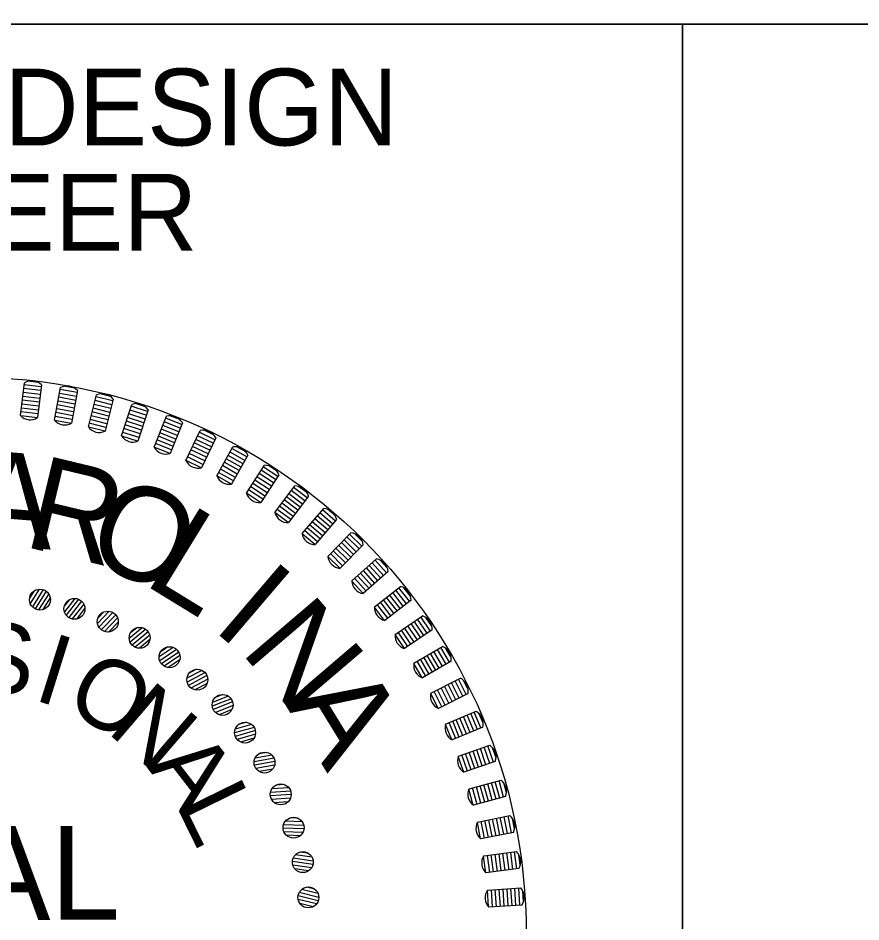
# Model space of a CAD drawing. Extents: x 2111095 to 2115970, y 670428 to 672393.
# Drawn here: x 2113107.3 to 2113162.1, y 672107.5 to 672166.4 of the extents above; entities that cross this region are included whole.
import ezdxf

# ---------------------------------------------------------------- set-up
doc = ezdxf.new("R2010")
doc.units = 0
doc.layers.add('Sheet PE Seal Cell', color=7, linetype='Continuous')
doc.layers.add('Sheet Typical CELL', color=7, linetype='Continuous')

msp = doc.modelspace()

# ---------------------------------------------------------------- linework, layer by layer
at = {"layer": 'Sheet PE Seal Cell'}
for p, q in [((2113107.43, 672140.486), (2113107.679, 672142.629)), ((2113108.585, 672142.648), (2113107.91, 672142.727)), ((2113108.714, 672141.864), (2113107.605, 672141.993)), ((2113108.743, 672142.117), (2113107.634, 672142.246)), ((2113108.773, 672142.37), (2113107.664, 672142.499)), ((2113108.788, 672142.501), (2113108.539, 672140.357)), ((2113109.651, 672140.191), (2113110.041, 672142.313)), ((2113111.115, 672141.982), (2113110.017, 672142.184)), ((2113110.946, 672142.272), (2113110.277, 672142.395)), ((2113111.138, 672142.112), (2113110.749, 672139.989)), ((2113108.655, 672141.358), (2113107.546, 672141.487)), ((2113108.685, 672141.611), (2113107.576, 672141.74)), ((2113110.977, 672141.231), (2113109.879, 672141.432)), ((2113111.023, 672141.481), (2113109.925, 672141.683)), ((2113111.069, 672141.732), (2113109.971, 672141.933)), ((2113111.847, 672139.749), (2113112.376, 672141.842)), ((2113113.363, 672141.193), (2113112.281, 672141.467)), ((2113113.426, 672141.44), (2113112.344, 672141.714)), ((2113113.277, 672141.741), (2113112.618, 672141.908)), ((2113113.458, 672141.568), (2113112.929, 672139.476)), ((2113108.597, 672140.852), (2113107.488, 672140.98)), ((2113108.626, 672141.105), (2113107.517, 672141.234)), ((2113110.885, 672140.73), (2113109.787, 672140.931)), ((2113110.931, 672140.98), (2113109.833, 672141.182)), ((2113113.239, 672140.7), (2113112.156, 672140.973)), ((2113113.301, 672140.947), (2113112.219, 672141.22)), ((2113114.009, 672139.164), (2113114.675, 672141.217)), ((2113115.618, 672140.505), (2113114.556, 672140.849)), ((2113115.696, 672140.747), (2113114.635, 672141.092)), ((2113115.567, 672141.057), (2113114.921, 672141.267)), ((2113115.737, 672140.872), (2113115.071, 672138.819)), ((2113108.524, 672140.347), (2113107.443, 672140.473)), ((2113108.567, 672140.599), (2113107.458, 672140.727)), ((2113110.793, 672140.228), (2113109.695, 672140.43)), ((2113110.839, 672140.479), (2113109.741, 672140.681)), ((2113113.051, 672139.959), (2113111.969, 672140.232)), ((2113113.114, 672140.206), (2113112.031, 672140.479)), ((2113113.176, 672140.453), (2113112.094, 672140.726)), ((2113115.46, 672140.02), (2113114.399, 672140.365)), ((2113115.539, 672140.263), (2113114.477, 672140.607)), ((2113116.127, 672138.437), (2113116.928, 672140.441)), ((2113117.916, 672139.905), (2113116.879, 672140.319)), ((2113117.808, 672140.223), (2113117.176, 672140.475)), ((2113110.733, 672139.98), (2113109.662, 672140.177)), ((2113112.913, 672139.468), (2113111.857, 672139.735)), ((2113112.989, 672139.712), (2113111.906, 672139.986)), ((2113115.224, 672139.293), (2113114.163, 672139.638)), ((2113115.303, 672139.536), (2113114.241, 672139.88)), ((2113115.382, 672139.778), (2113114.32, 672140.123)), ((2113117.727, 672139.432), (2113116.69, 672139.846)), ((2113117.821, 672139.669), (2113116.785, 672140.083)), ((2113117.965, 672140.027), (2113117.164, 672138.023)), ((2113115.054, 672138.813), (2113114.019, 672139.149)), ((2113115.146, 672139.051), (2113114.084, 672139.396)), ((2113117.443, 672138.722), (2113116.407, 672139.137)), ((2113117.538, 672138.959), (2113116.501, 672139.373)), ((2113117.632, 672139.196), (2113116.596, 672139.61)), ((2113118.193, 672137.572), (2113119.125, 672139.519)), ((2113119.965, 672138.689), (2113118.958, 672139.17)), ((2113120.075, 672138.918), (2113119.068, 672139.4)), ((2113119.988, 672139.242), (2113119.375, 672139.536)), ((2113117.254, 672138.249), (2113116.218, 672138.663)), ((2113117.349, 672138.486), (2113116.312, 672138.9)), ((2113119.635, 672137.999), (2113118.628, 672138.481)), ((2113119.745, 672138.229), (2113118.738, 672138.711)), ((2113119.855, 672138.459), (2113118.848, 672138.941)), ((2113120.132, 672139.037), (2113119.2, 672137.09)), ((2113120.198, 672136.572), (2113121.256, 672138.453)), ((2113122.099, 672138.12), (2113121.506, 672138.453)), ((2113117.147, 672138.018), (2113116.136, 672138.422)), ((2113119.416, 672137.54), (2113118.409, 672138.021)), ((2113119.525, 672137.77), (2113118.518, 672138.251)), ((2113121.914, 672137.347), (2113120.942, 672137.894)), ((2113122.039, 672137.569), (2113121.066, 672138.116)), ((2113122.229, 672137.906), (2113121.171, 672136.025)), ((2113122.164, 672137.791), (2113121.191, 672138.338)), ((2113119.183, 672137.086), (2113118.201, 672137.556)), ((2113119.306, 672137.31), (2113118.299, 672137.792)), ((2113121.665, 672136.903), (2113120.692, 672137.45)), ((2113121.79, 672137.125), (2113120.817, 672137.672)), ((2113121.29, 672136.237), (2113120.317, 672136.784)), ((2113121.415, 672136.459), (2113120.442, 672137.006)), ((2113121.54, 672136.681), (2113120.567, 672137.228)), ((2113122.132, 672135.442), (2113123.312, 672137.249)), ((2113123.896, 672136.102), (2113122.961, 672136.712)), ((2113124.035, 672136.315), (2113123.1, 672136.925)), ((2113124.174, 672136.528), (2113123.24, 672137.139)), ((2113124.131, 672136.861), (2113123.562, 672137.233)), ((2113121.153, 672136.022), (2113120.204, 672136.555)), ((2113123.617, 672135.675), (2113122.683, 672136.286)), ((2113123.757, 672135.888), (2113122.822, 672136.499)), ((2113124.246, 672136.638), (2113123.066, 672134.831)), ((2113123.199, 672135.035), (2113122.265, 672135.646)), ((2113123.339, 672135.249), (2113122.404, 672135.859)), ((2113123.478, 672135.462), (2113122.543, 672136.072)), ((2113123.987, 672134.186), (2113125.283, 672135.911)), ((2113125.943, 672134.932), (2113125.051, 672135.603)), ((2113126.097, 672135.135), (2113125.204, 672135.806)), ((2113126.075, 672135.47), (2113125.532, 672135.879)), ((2113123.049, 672134.83), (2113122.137, 672135.425)), ((2113125.484, 672134.321), (2113124.592, 672134.992)), ((2113125.637, 672134.525), (2113124.745, 672135.195)), ((2113126.176, 672135.24), (2113124.879, 672133.515)), ((2113125.79, 672134.728), (2113124.898, 672135.399)), ((2113125.025, 672133.71), (2113124.133, 672134.381)), ((2113125.178, 672133.914), (2113124.286, 672134.584)), ((2113125.331, 672134.117), (2113124.439, 672134.788)), ((2113125.754, 672132.811), (2113127.162, 672134.446)), ((2113127.923, 672133.618), (2113127.077, 672134.347)), ((2113127.923, 672133.954), (2113127.408, 672134.397)), ((2113124.861, 672133.515), (2113123.991, 672134.169)), ((2113127.424, 672133.039), (2113126.578, 672133.768)), ((2113127.59, 672133.232), (2113126.744, 672133.961)), ((2113127.756, 672133.425), (2113126.91, 672134.154)), ((2113126.925, 672132.46), (2113126.079, 672133.188)), ((2113127.092, 672132.653), (2113126.246, 672133.381)), ((2113127.258, 672132.846), (2113126.412, 672133.574)), ((2113128.008, 672133.718), (2113126.6, 672132.082)), ((2113126.583, 672132.083), (2113125.758, 672132.793)), ((2113126.759, 672132.267), (2113125.913, 672132.995)), ((2113127.427, 672131.321), (2113128.94, 672132.86)), ((2113129.466, 672131.802), (2113128.67, 672132.585)), ((2113129.644, 672131.984), (2113128.848, 672132.767)), ((2113129.667, 672132.319), (2113129.182, 672132.795)), ((2113128.93, 672131.257), (2113128.134, 672132.04)), ((2113129.736, 672132.078), (2113128.223, 672130.539)), ((2113129.109, 672131.439), (2113128.313, 672132.222)), ((2113129.287, 672131.621), (2113128.491, 672132.403)), ((2113128.394, 672130.713), (2113127.598, 672131.495)), ((2113128.573, 672130.894), (2113127.777, 672131.677)), ((2113128.751, 672131.076), (2113127.955, 672131.858)), ((2113128.206, 672130.541), (2113127.429, 672131.304)), ((2113128.998, 672129.725), (2113130.61, 672131.16)), ((2113131.064, 672130.07), (2113130.321, 672130.904)), ((2113131.254, 672130.24), (2113130.512, 672131.073)), ((2113131.299, 672130.572), (2113130.847, 672131.08)), ((2113130.303, 672129.392), (2113129.561, 672130.226)), ((2113131.352, 672130.327), (2113129.741, 672128.891)), ((2113130.493, 672129.562), (2113129.751, 672130.395)), ((2113130.684, 672129.731), (2113129.941, 672130.565)), ((2113130.874, 672129.901), (2113130.131, 672130.734)), ((2113129.723, 672128.894), (2113128.999, 672129.707)), ((2113129.923, 672129.053), (2113129.18, 672129.887)), ((2113130.113, 672129.223), (2113129.37, 672130.056)), ((2113108.311, 672129.066), (2113108.02, 672128.6)), ((2113108.651, 672129.183), (2113108.065, 672128.243)), ((2113108.9, 672129.152), (2113108.201, 672128.034)), ((2113109.102, 672129.048), (2113108.384, 672127.897)), ((2113130.461, 672128.028), (2113132.163, 672129.354)), ((2113132.544, 672128.236), (2113131.859, 672129.117)), ((2113132.745, 672128.392), (2113132.059, 672129.273)), ((2113132.812, 672128.721), (2113132.395, 672129.258)), ((2113109.263, 672128.877), (2113108.608, 672127.828)), ((2113109.366, 672128.613), (2113108.89, 672127.852)), ((2113110.618, 672128.502), (2113110.28, 672128.069)), ((2113110.968, 672128.582), (2113110.287, 672127.709)), ((2113111.212, 672128.526), (2113110.401, 672127.487)), ((2113131.74, 672127.61), (2113131.055, 672128.491)), ((2113132.849, 672128.473), (2113131.146, 672127.147)), ((2113131.941, 672127.766), (2113131.256, 672128.647)), ((2113132.142, 672127.923), (2113131.457, 672128.804)), ((2113132.343, 672128.079), (2113131.658, 672128.96)), ((2113111.402, 672128.401), (2113110.568, 672127.332)), ((2113111.544, 672128.214), (2113110.783, 672127.24)), ((2113111.619, 672127.941), (2113111.066, 672127.234)), ((2113131.129, 672127.151), (2113130.46, 672128.01)), ((2113131.339, 672127.297), (2113130.653, 672128.178)), ((2113131.54, 672127.453), (2113130.854, 672128.334)), ((2113113.21, 672127.743), (2113112.441, 672126.946)), ((2113112.853, 672127.7), (2113112.471, 672127.304)), ((2113113.446, 672127.661), (2113112.531, 672126.713)), ((2113113.623, 672127.517), (2113112.681, 672126.542)), ((2113113.744, 672127.317), (2113112.886, 672126.427)), ((2113131.807, 672126.238), (2113133.594, 672127.449)), ((2113134.111, 672126.451), (2113133.485, 672127.375)), ((2113134.2, 672126.774), (2113133.818, 672127.337)), ((2113113.79, 672127.037), (2113113.166, 672126.391)), ((2113133.268, 672125.879), (2113132.641, 672126.803)), ((2113133.479, 672126.022), (2113132.852, 672126.946)), ((2113133.689, 672126.165), (2113133.063, 672127.089)), ((2113133.9, 672126.308), (2113133.274, 672127.232)), ((2113115.351, 672126.674), (2113114.503, 672125.962)), ((2113115.578, 672126.568), (2113114.568, 672125.72)), ((2113114.991, 672126.668), (2113114.571, 672126.315)), ((2113115.738, 672126.407), (2113114.699, 672125.534)), ((2113115.838, 672126.194), (2113114.891, 672125.399)), ((2113132.416, 672125.319), (2113131.806, 672126.22)), ((2113132.635, 672125.451), (2113132.009, 672126.375)), ((2113132.846, 672125.593), (2113132.22, 672126.518)), ((2113133.057, 672125.736), (2113132.431, 672126.66)), ((2113134.22, 672126.525), (2113132.433, 672125.314)), ((2113115.854, 672125.912), (2113115.167, 672125.334)), ((2113117.369, 672125.387), (2113116.451, 672124.768)), ((2113117.583, 672125.258), (2113116.49, 672124.52)), ((2113117.011, 672125.419), (2113116.555, 672125.112)), ((2113117.726, 672125.081), (2113116.602, 672124.322)), ((2113133.033, 672124.363), (2113134.895, 672125.453)), ((2113134.686, 672124.037), (2113134.122, 672125.001)), ((2113134.906, 672124.166), (2113134.342, 672125.129)), ((2113135.126, 672124.294), (2113134.562, 672125.258)), ((2113135.346, 672124.423), (2113134.782, 672125.387)), ((2113135.455, 672124.74), (2113135.112, 672125.327)), ((2113117.803, 672124.859), (2113116.778, 672124.167)), ((2113117.79, 672124.576), (2113117.046, 672124.074)), ((2113133.58, 672123.406), (2113133.03, 672124.346)), ((2113133.807, 672123.523), (2113133.243, 672124.486)), ((2113134.026, 672123.651), (2113133.463, 672124.615)), ((2113135.459, 672124.489), (2113133.596, 672123.4)), ((2113134.246, 672123.78), (2113133.683, 672124.743)), ((2113134.466, 672123.909), (2113133.902, 672124.872)), ((2113119.241, 672123.896), (2113118.264, 672123.376)), ((2113119.441, 672123.746), (2113118.277, 672123.126)), ((2113118.888, 672123.965), (2113118.403, 672123.707)), ((2113119.564, 672123.554), (2113118.367, 672122.917)), ((2113119.618, 672123.326), (2113118.526, 672122.745)), ((2113134.132, 672122.411), (2113136.062, 672123.376)), ((2113136.216, 672122.204), (2113135.717, 672123.203)), ((2113136.443, 672122.318), (2113135.945, 672123.317)), ((2113136.574, 672122.627), (2113136.27, 672123.236)), ((2113119.575, 672123.046), (2113118.782, 672122.624)), ((2113135.076, 672121.635), (2113134.577, 672122.634)), ((2113135.304, 672121.749), (2113134.805, 672122.748)), ((2113135.532, 672121.863), (2113135.033, 672122.862)), ((2113135.76, 672121.977), (2113135.261, 672122.975)), ((2113135.988, 672122.091), (2113135.489, 672123.089)), ((2113121.13, 672122.047), (2113119.908, 672121.553)), ((2113120.947, 672122.218), (2113119.921, 672121.803)), ((2113120.604, 672122.324), (2113120.094, 672122.118)), ((2113134.614, 672121.42), (2113134.128, 672122.394)), ((2113134.848, 672121.522), (2113134.349, 672122.52)), ((2113136.561, 672122.377), (2113134.63, 672121.413)), ((2113121.233, 672121.844), (2113119.976, 672121.336)), ((2113121.262, 672121.611), (2113120.116, 672121.148)), ((2113121.19, 672121.337), (2113120.358, 672121.001)), ((2113135.099, 672120.391), (2113137.089, 672121.226)), ((2113136.695, 672119.85), (2113136.263, 672120.879)), ((2113136.93, 672119.948), (2113136.498, 672120.978)), ((2113137.165, 672120.047), (2113136.733, 672121.076)), ((2113137.4, 672120.145), (2113136.968, 672121.175)), ((2113137.55, 672120.445), (2113137.287, 672121.072)), ((2113122.469, 672120.37), (2113121.405, 672120.065)), ((2113122.138, 672120.511), (2113121.61, 672120.36)), ((2113135.515, 672119.37), (2113135.094, 672120.374)), ((2113135.755, 672119.456), (2113135.324, 672120.485)), ((2113135.99, 672119.554), (2113135.559, 672120.584)), ((2113136.225, 672119.653), (2113135.793, 672120.682)), ((2113136.46, 672119.751), (2113136.028, 672120.781)), ((2113122.633, 672120.181), (2113121.366, 672119.818)), ((2113122.714, 672119.969), (2113121.41, 672119.594)), ((2113122.719, 672119.734), (2113121.53, 672119.393)), ((2113137.521, 672120.196), (2113135.531, 672119.362)), ((2113122.618, 672119.469), (2113121.756, 672119.222)), ((2113123.475, 672118.549), (2113122.934, 672118.453)), ((2113135.931, 672118.311), (2113137.972, 672119.013)), ((2113136.765, 672117.418), (2113136.402, 672118.473)), ((2113137.006, 672117.5), (2113136.643, 672118.556)), ((2113137.247, 672117.583), (2113136.884, 672118.639)), ((2113137.488, 672117.666), (2113137.125, 672118.722)), ((2113137.728, 672117.749), (2113137.366, 672118.804)), ((2113137.969, 672117.832), (2113137.607, 672118.887)), ((2113138.21, 672117.914), (2113137.848, 672118.97)), ((2113138.38, 672118.203), (2113138.159, 672118.846)), ((2113123.932, 672118.169), (2113122.634, 672117.94)), ((2113123.99, 672117.949), (2113122.655, 672117.713)), ((2113123.789, 672118.374), (2113122.698, 672118.181)), ((2113136.279, 672117.265), (2113135.925, 672118.295)), ((2113136.524, 672117.335), (2113136.161, 672118.391)), ((2113138.335, 672117.957), (2113136.294, 672117.256)), ((2113123.971, 672117.715), (2113122.753, 672117.5)), ((2113123.843, 672117.462), (2113122.959, 672117.306)), ((2113136.623, 672116.181), (2113138.706, 672116.746)), ((2113138.872, 672115.634), (2113138.579, 672116.712)), ((2113124.893, 672116.25), (2113123.788, 672116.173)), ((2113124.599, 672116.457), (2113124.051, 672116.419)), ((2113136.901, 672115.114), (2113136.616, 672116.165)), ((2113137.151, 672115.168), (2113136.859, 672116.245)), ((2113137.397, 672115.234), (2113137.104, 672116.312)), ((2113137.642, 672115.301), (2113137.35, 672116.378)), ((2113137.888, 672115.368), (2113137.596, 672116.445)), ((2113138.134, 672115.434), (2113137.842, 672116.512)), ((2113138.38, 672115.501), (2113138.088, 672116.578)), ((2113138.626, 672115.568), (2113138.334, 672116.645)), ((2113139.06, 672115.912), (2113138.882, 672116.568)), ((2113125.049, 672115.807), (2113123.696, 672115.712)), ((2113125.014, 672116.032), (2113123.699, 672115.939)), ((2113125.005, 672115.576), (2113123.772, 672115.49)), ((2113138.999, 672115.669), (2113136.916, 672115.104)), ((2113124.852, 672115.338), (2113123.956, 672115.275)), ((2113137.174, 672114.01), (2113139.289, 672114.436)), ((2113139.131, 672113.265), (2113138.911, 672114.36)), ((2113139.381, 672113.316), (2113139.161, 672114.41)), ((2113125.867, 672113.793), (2113124.549, 672113.839)), ((2113125.769, 672114.023), (2113124.662, 672114.062)), ((2113125.498, 672114.26), (2113124.949, 672114.279)), ((2113137.38, 672112.927), (2113137.166, 672113.994)), ((2113137.633, 672112.964), (2113137.413, 672114.058)), ((2113137.883, 672113.014), (2113137.662, 672114.108)), ((2113138.132, 672113.064), (2113137.912, 672114.159)), ((2113138.382, 672113.115), (2113138.162, 672114.209)), ((2113138.632, 672113.165), (2113138.411, 672114.259)), ((2113138.881, 672113.215), (2113138.661, 672114.31)), ((2113139.587, 672113.58), (2113139.453, 672114.246)), ((2113125.878, 672113.565), (2113124.522, 672113.612)), ((2113125.81, 672113.341), (2113124.574, 672113.384)), ((2113125.633, 672113.12), (2113124.736, 672113.151)), ((2113139.51, 672113.342), (2113137.394, 672112.916)), ((2113126.163, 672111.98), (2113125.619, 672112.056)), ((2113137.579, 672111.807), (2113139.719, 672112.092)), ((2113138.978, 672110.868), (2113138.831, 672111.974)), ((2113139.231, 672110.901), (2113139.083, 672112.008)), ((2113139.483, 672110.935), (2113139.336, 672112.041)), ((2113139.736, 672110.969), (2113139.588, 672112.075)), ((2113126.468, 672111.25), (2113125.125, 672111.438)), ((2113126.481, 672111.477), (2113125.175, 672111.66)), ((2113126.407, 672111.717), (2113125.311, 672111.87)), ((2113137.714, 672110.713), (2113137.57, 672111.792)), ((2113137.968, 672110.733), (2113137.821, 672111.839)), ((2113138.221, 672110.767), (2113138.073, 672111.873)), ((2113138.473, 672110.8), (2113138.326, 672111.907)), ((2113138.726, 672110.834), (2113138.578, 672111.94)), ((2113139.959, 672111.218), (2113139.869, 672111.892)), ((2113126.377, 672111.034), (2113125.153, 672111.205)), ((2113126.178, 672110.833), (2113125.289, 672110.957)), ((2113139.866, 672110.986), (2113137.727, 672110.701)), ((2113126.801, 672109.356), (2113125.727, 672109.624)), ((2113126.585, 672109.643), (2113126.052, 672109.776)), ((2113137.838, 672109.582), (2113139.992, 672109.726)), ((2113138.41, 672108.502), (2113138.336, 672109.615)), ((2113138.664, 672108.518), (2113138.59, 672109.632)), ((2113138.918, 672108.535), (2113138.844, 672109.649)), ((2113139.172, 672108.552), (2113139.098, 672109.666)), ((2113139.426, 672108.569), (2113139.352, 672109.683)), ((2113139.68, 672108.586), (2113139.606, 672109.7)), ((2113139.935, 672108.603), (2113139.861, 672109.717)), ((2113126.812, 672108.886), (2113125.496, 672109.213)), ((2113126.849, 672109.11), (2113125.57, 672109.429)), ((2113137.9, 672108.482), (2113137.828, 672109.568)), ((2113138.155, 672108.485), (2113138.081, 672109.599)), ((2113140.174, 672108.838), (2113140.129, 672109.516)), ((2113126.699, 672108.68), (2113125.5, 672108.979)), ((2113126.48, 672108.501), (2113125.609, 672108.718)), ((2113140.066, 672108.612), (2113137.912, 672108.469))]:
    msp.add_line(p, q, dxfattribs=at)
for centre, radius in [((2113104.13, 672106.779), 36.215), ((2113108.694, 672128.503), 0.681), ((2113110.94, 672127.902), 0.681), ((2113113.11, 672127.07), 0.681), ((2113115.181, 672126.015), 0.681), ((2113117.131, 672124.749), 0.681), ((2113118.938, 672123.287), 0.681), ((2113120.583, 672121.643), 0.681), ((2113122.046, 672119.837), 0.681), ((2113123.313, 672117.888), 0.681), ((2113124.368, 672115.817), 0.681), ((2113125.202, 672113.647), 0.681), ((2113125.804, 672111.402), 0.681), ((2113126.168, 672109.106), 0.681)]:
    msp.add_circle(centre, radius, dxfattribs=at)
for centre, radius, start, end in [((2113108.149, 672141.836), 0.922, 46.11223, 120.6532), ((2113110.457, 672141.491), 0.922, 42.32275, 116.86372), ((2113112.737, 672140.994), 0.922, 38.53328, 113.07425), ((2113114.98, 672140.347), 0.922, 34.74381, 109.28477), ((2113108.063, 672141.094), 0.878, 223.88597, 302.87946), ((2113117.174, 672139.553), 0.922, 30.95433, 105.4953), ((2113110.322, 672140.756), 0.878, 220.09649, 299.08998), ((2113112.554, 672140.269), 0.878, 216.30702, 295.30051), ((2113114.749, 672139.636), 0.878, 212.51754, 291.51104), ((2113119.312, 672138.616), 0.922, 27.16486, 101.70583), ((2113121.383, 672137.54), 0.922, 23.37539, 97.91635), ((2113116.897, 672138.859), 0.878, 208.72807, 287.72156), ((2113118.989, 672137.942), 0.878, 204.9386, 283.93209), ((2113123.378, 672136.329), 0.922, 19.58591, 94.12688), ((2113121.016, 672136.889), 0.878, 201.14912, 280.14262), ((2113125.289, 672134.99), 0.922, 15.79644, 90.33741), ((2113122.969, 672135.704), 0.878, 197.35965, 276.35314), ((2113127.107, 672133.526), 0.922, 12.00696, 86.54793), ((2113124.84, 672134.392), 0.878, 193.57018, 272.56367), ((2113126.619, 672132.96), 0.878, 189.7807, 268.77419), ((2113128.824, 672131.946), 0.922, 8.21749, 82.75846), ((2113128.3, 672131.413), 0.878, 185.99123, 264.98472), ((2113130.433, 672130.256), 0.922, 4.42802, 78.96899), ((2113129.875, 672129.759), 0.878, 182.20175, 261.19525), ((2113131.927, 672128.463), 0.922, 0.63854, 75.17951), ((2113131.338, 672128.004), 0.878, 178.41228, 257.40577), ((2113133.3, 672126.575), 0.922, 356.84907, 71.39004), ((2113132.681, 672126.156), 0.878, 174.62281, 253.6163), ((2113134.544, 672124.601), 0.922, 353.0596, 67.60056), ((2113133.899, 672124.223), 0.878, 170.83333, 249.82683), ((2113135.655, 672122.549), 0.922, 349.27012, 63.81109), ((2113134.987, 672122.215), 0.878, 167.04386, 246.03735), ((2113136.629, 672120.427), 0.922, 345.48065, 60.02162), ((2113135.939, 672120.138), 0.878, 163.25439, 242.24788), ((2113137.46, 672118.247), 0.922, 341.69117, 56.23214), ((2113136.753, 672118.004), 0.878, 159.46491, 238.4584), ((2113138.145, 672116.016), 0.922, 337.9017, 52.44267), ((2113137.423, 672115.82), 0.878, 155.67544, 234.66893), ((2113138.681, 672113.744), 0.922, 334.11223, 48.6532), ((2113137.948, 672113.597), 0.878, 151.88597, 230.87946), ((2113139.065, 672111.442), 0.922, 330.32275, 44.86372), ((2113138.324, 672111.343), 0.878, 148.09649, 227.08998), ((2113139.297, 672109.12), 0.922, 326.53328, 41.07425), ((2113138.551, 672109.07), 0.878, 144.30702, 223.30051)]:
    msp.add_arc(centre, radius, start, end, dxfattribs=at)
at = {"layer": 'Sheet Typical CELL'}
msp.add_line((2113150.523, 672165.983), (2113150.523, 672053.533), dxfattribs=at)
for points in [[(2113050.473, 672191.033), (2113250.523, 672191.033), (2113250.523, 672165.983), (2113050.473, 672165.983)], [(2113050.473, 672165.983), (2113150.523, 672165.983), (2113150.523, 672053.483), (2113050.473, 672053.483)], [(2113150.523, 672165.983), (2113250.523, 672165.983), (2113250.523, 672053.483), (2113150.523, 672053.483)]]:
    msp.add_lwpolyline(points, close=True, dxfattribs=at)

# ---------------------------------------------------------------- texts
at = {"layer": 'Sheet PE Seal Cell'}
for s, height, rotation, p in [('A', 6.113, 355.51429, (2113103.973, 672132.185)), ('R', 6.113, 346.51429, (2113107.495, 672131.998)), ('O', 6.113, 337.51429, (2113111.399, 672131.154)), ('L', 6.113, 328.51429, (2113115.32, 672129.587)), ('I', 6.113, 319.51429, (2113119.813, 672126.641)), ('N', 6.113, 310.51429, (2113121.667, 672125.175)), ('S', 4.585, 354.20784, (2113104.043, 672122.616)), ('I', 4.585, 342.59494, (2113108.169, 672122.006)), ('O', 4.585, 330.98203, (2113110.148, 672121.428)), ('N', 4.585, 319.36913, (2113112.973, 672119.907)), ('A', 6.113, 301.51429, (2113124.572, 672121.801)), ('A', 4.585, 307.75623, (2113115.634, 672117.589)), ('L', 4.585, 296.14332, (2113117.502, 672115.19)), ('SEAL', 6.1134, 0.01429, (2113093.019, 672107.642))]:
    msp.add_text(s, height=height, rotation=rotation, dxfattribs=at).set_placement(p)
at = {"layer": 'Sheet Typical CELL'}
for s, p in [('ROADWAY DESIGN', (2113069.973, 672158.083)), ('ENGINEER', (2113084.023, 672151.233))]:
    msp.add_text(s, height=5.0001, dxfattribs=at).set_placement(p)

doc.saveas('drawing.dxf')
